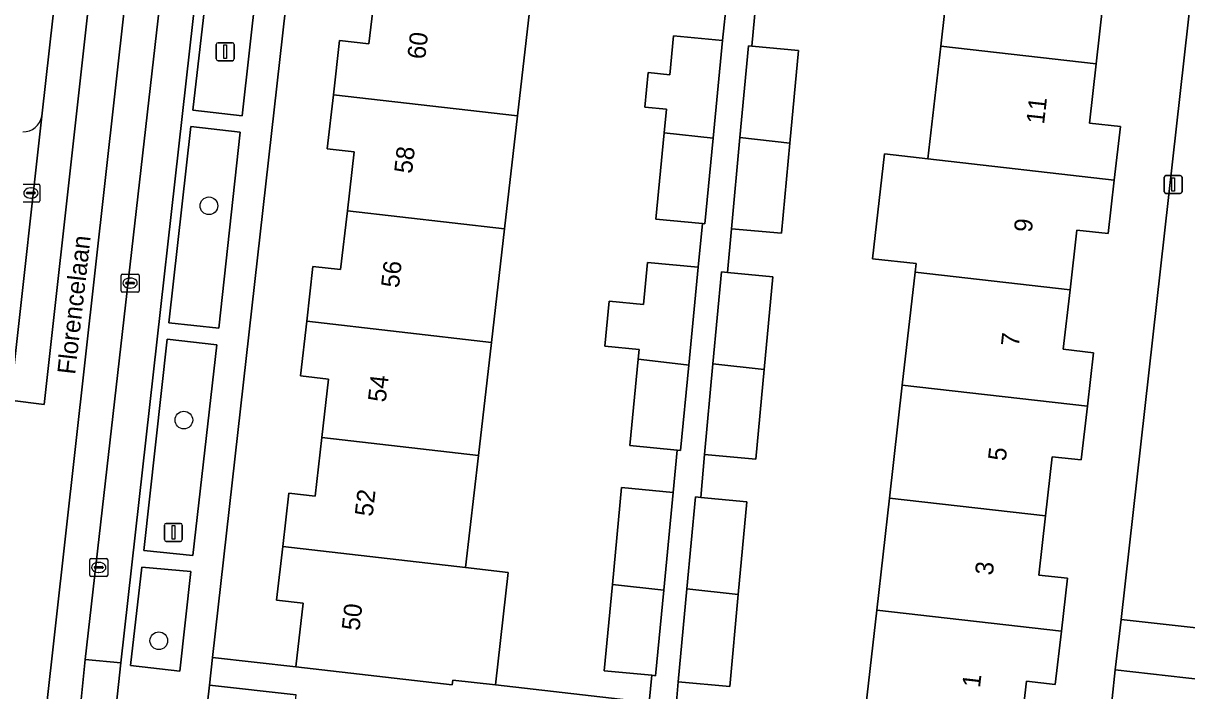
# Model space of a CAD drawing. Extents: x 162082 to 163401, y 388089 to 388636.
# Drawn here: x 162729.5 to 162794, y 388507 to 388544.1 of the extents above; entities that cross this region are included whole.
import ezdxf

# ---------------------------------------------------------------- set-up
doc = ezdxf.new("R2010")
doc.units = 0
for name, color, linetype in [('IMGEO_Boom', 7, 'Continuous'), ('IMGEO_Erf', 7, 'Continuous'), ('IMGEO_Groenvoorziening', 7, 'Continuous'), ('IMGEO_Kolk', 7, 'Continuous'), ('IMGEO_Lichtmast', 7, 'Continuous'), ('IMGEO_Openbare_ruimte_label', 7, 'Continuous'), ('IMGEO_Pand', 7, 'Continuous'), ('IMGEO_Pand_nummerreeks', 7, 'Continuous'), ('IMGEO_Parkeervlak_open', 7, 'Continuous'), ('IMGEO_Rijbaan_lokaal_gesloten', 7, 'Continuous'), ('IMGEO_Rijbaan_lokaal_open', 7, 'Continuous'), ('IMGEO_Voetpad_open', 7, 'Continuous')]:
    doc.layers.add(name, color=color, linetype=linetype)

msp = doc.modelspace()

# ---------------------------------------------------------------- linework, layer by layer
at = {"layer": 'IMGEO_Boom'}
for centre in [(162739.754, 388533.943), (162738.364, 388522.057), (162736.974, 388509.816)]:
    msp.add_circle(centre, 0.489, dxfattribs=at)
at = {"layer": 'IMGEO_Erf'}
for points in [[(162745.878, 388561.46), (162739.957, 388508.884), (162744.578, 388508.364), (162744.984, 388511.902), (162743.511, 388512.071), (162743.851, 388515.038), (162744.192, 388518.007), (162745.652, 388517.839), (162746.024, 388521.085), (162746.396, 388524.33), (162744.83, 388524.509), (162745.179, 388527.545), (162745.527, 388530.58), (162747.062, 388530.403), (162747.436, 388533.665), (162747.811, 388536.927), (162746.316, 388537.099), (162746.661, 388540.105), (162747.005, 388543.109), (162748.636, 388542.922), (162749.011, 388546.188)], [(162789.54, 388503.424), (162790.046, 388508.201), (162790.361, 388511.004), (162795.399, 388555.856)], [(162776.059, 388504.867), (162776.811, 388511.504), (162777.516, 388517.726), (162778.226, 388523.988), (162778.937, 388530.267), (162778.99, 388530.733), (162776.58, 388531.006), (162777.238, 388536.817), (162779.648, 388536.543), (162780.357, 388542.8), (162781.07, 388549.092)], [(162757.592, 388545.203), (162756.873, 388538.933), (162756.154, 388532.665), (162755.431, 388526.368), (162754.711, 388520.088), (162753.998, 388513.874), (162756.364, 388513.603), (162755.649, 388507.365), (162764.19, 388506.386), (162764.321, 388507.898), (162761.684, 388508.149), (162762.14, 388512.94), (162762.652, 388518.312), (162765.507, 388518.04), (162765.731, 388520.394), (162763.117, 388520.643), (162763.573, 388525.433), (162763.624, 388525.967), (162761.717, 388526.149), (162761.956, 388528.655), (162763.863, 388528.473), (162764.085, 388530.806), (162766.896, 388530.538), (162767.137, 388532.963), (162764.559, 388533.208), (162765.015, 388537.999), (162765.139, 388539.305), (162763.94, 388539.419), (162764.123, 388541.33), (162765.322, 388541.216), (162765.527, 388543.371), (162768.247, 388543.112), (162768.485, 388545.392)], [(162770.105, 388545.184), (162769.883, 388542.803), (162772.469, 388542.564), (162771.992, 388537.413), (162771.53, 388532.417), (162768.748, 388532.674), (162768.535, 388530.241), (162771.036, 388530.01), (162770.56, 388524.86), (162770.1, 388519.887), (162767.256, 388520.151), (162767.044, 388517.766), (162769.604, 388517.529), (162769.126, 388512.377), (162768.654, 388507.273), (162765.798, 388507.537), (162765.675, 388506.212)], [(162789.362, 388545.114), (162788.988, 388541.82), (162788.615, 388538.527), (162790.327, 388538.333), (162789.991, 388535.368), (162789.655, 388532.398), (162787.908, 388532.596), (162787.534, 388529.29), (162787.159, 388525.984), (162788.833, 388525.794), (162788.496, 388522.82), (162788.159, 388519.844), (162786.549, 388520.026), (162786.177, 388516.742), (162785.805, 388513.462), (162787.385, 388513.283), (162787.051, 388510.34), (162786.717, 388507.393), (162785.114, 388507.574), (162784.697, 388503.888)], [(162786.382, 388500.073), (162786.604, 388502.153), (162781.395, 388502.707), (162781.106, 388500.167), (162776.026, 388500.742), (162771.206, 388501.288), (162771.494, 388503.827), (162768.909, 388504.11), (162768.696, 388501.874), (162763.594, 388502.359), (162758.632, 388502.832), (162758.858, 388505.209), (162756.271, 388505.492), (162755.985, 388502.961), (162750.924, 388503.535), (162744.309, 388504.284), (162744.595, 388506.815), (162739.785, 388507.361), (162737.36, 388485.969)]]:
    msp.add_lwpolyline(points, dxfattribs=at)
at = {"layer": 'IMGEO_Groenvoorziening'}
for points in [[(162742.779, 388549.542), (162740.074, 388549.861), (162738.863, 388539.243), (162741.596, 388538.927)], [(162741.489, 388538.023), (162738.747, 388538.334), (162737.538, 388527.456), (162740.301, 388527.149)], [(162740.194, 388526.236), (162737.436, 388526.539), (162736.136, 388514.826), (162738.86, 388514.54)], [(162738.748, 388513.664), (162736.03, 388513.903), (162735.408, 388508.44), (162738.139, 388508.128)]]:
    msp.add_lwpolyline(points, close=True, dxfattribs=at)
at = {"layer": 'IMGEO_Kolk'}
for p, q in [((162729.454, 388535.151), (162730.306, 388535.151)), ((162729.867, 388534.931), (162729.892, 388534.931)), ((162730.38, 388535.077), (162730.38, 388534.225)), ((162729.638, 388534.645), (162729.638, 388534.657)), ((162730.076, 388534.608), (162729.678, 388534.608)), ((162729.681, 388534.694), (162730.079, 388534.694)), ((162729.89, 388534.371), (162729.865, 388534.371)), ((162730.122, 388534.657), (162730.122, 388534.645)), ((162730.306, 388534.151), (162729.454, 388534.151)), ((162734.878, 388529.229), (162734.878, 388530.081)), ((162734.953, 388530.155), (162735.805, 388530.155)), ((162735.366, 388529.935), (162735.391, 388529.935)), ((162735.879, 388530.081), (162735.879, 388529.229)), ((162735.805, 388529.155), (162734.953, 388529.155)), ((162735.137, 388529.649), (162735.137, 388529.661)), ((162735.575, 388529.612), (162735.177, 388529.612)), ((162735.18, 388529.698), (162735.578, 388529.698)), ((162735.389, 388529.375), (162735.364, 388529.375)), ((162735.621, 388529.661), (162735.621, 388529.649)), ((162733.138, 388513.459), (162733.138, 388514.311)), ((162733.213, 388514.385), (162734.065, 388514.385)), ((162734.139, 388514.311), (162734.139, 388513.459)), ((162733.397, 388513.879), (162733.397, 388513.891)), ((162733.835, 388513.842), (162733.437, 388513.842)), ((162733.44, 388513.928), (162733.838, 388513.928)), ((162733.626, 388514.165), (162733.651, 388514.165)), ((162733.881, 388513.891), (162733.881, 388513.879)), ((162734.065, 388513.385), (162733.213, 388513.385)), ((162733.649, 388513.605), (162733.624, 388513.605))]:
    msp.add_line(p, q, dxfattribs=at)
for points in [[(162729.454, 388535.151), (162730.306, 388535.151)], [(162730.38, 388535.077), (162730.38, 388534.225)], [(162730.306, 388534.151), (162729.454, 388534.151)], [(162734.878, 388529.229), (162734.878, 388530.081)], [(162734.953, 388530.155), (162735.805, 388530.155)], [(162735.879, 388530.081), (162735.879, 388529.229)], [(162735.805, 388529.155), (162734.953, 388529.155)], [(162733.138, 388513.459), (162733.138, 388514.311)], [(162733.213, 388514.385), (162734.065, 388514.385)], [(162734.139, 388514.311), (162734.139, 388513.459)], [(162734.065, 388513.385), (162733.213, 388513.385)]]:
    msp.add_lwpolyline(points, dxfattribs=at)
for centre, radius, start, end in [((162730.304, 388535.075), 0.0765, 1.55205, 88.44795), ((162730.304, 388535.075), 0.0765, 1.55205, 88.44795), ((162729.678, 388534.654), 0.0403, 85.87752, 175.75265), ((162729.675, 388534.644), 0.0366, 178.93798, 274.71019), ((162730.079, 388534.651), 0.043, 264.86636, 352.45326), ((162730.083, 388534.656), 0.0386, 1.73085, 96.63898), ((162730.304, 388534.227), 0.0765, 271.55205, 358.44795), ((162730.304, 388534.227), 0.0765, 271.55205, 358.44795), ((162734.955, 388530.079), 0.0765, 91.55205, 178.44795), ((162734.955, 388530.079), 0.0765, 91.55205, 178.44795), ((162735.803, 388530.079), 0.0765, 1.55205, 88.44795), ((162735.803, 388530.079), 0.0765, 1.55205, 88.44795), ((162734.955, 388529.231), 0.0765, 181.55205, 268.44795), ((162734.955, 388529.231), 0.0765, 181.55205, 268.44795), ((162735.177, 388529.658), 0.0403, 85.87752, 175.75265), ((162735.174, 388529.648), 0.0366, 178.93798, 274.71019), ((162735.578, 388529.655), 0.043, 264.86636, 352.45326), ((162735.582, 388529.66), 0.0386, 1.73085, 96.63898), ((162735.803, 388529.231), 0.0765, 271.55205, 358.44795), ((162735.803, 388529.231), 0.0765, 271.55205, 358.44795), ((162733.215, 388514.309), 0.0765, 91.55205, 178.44795), ((162733.215, 388514.309), 0.0765, 91.55205, 178.44795), ((162734.063, 388514.309), 0.0765, 1.55205, 88.44795), ((162734.063, 388514.309), 0.0765, 1.55205, 88.44795), ((162733.437, 388513.888), 0.0403, 85.87752, 175.75265), ((162733.434, 388513.878), 0.0366, 178.93798, 274.71019), ((162733.838, 388513.885), 0.043, 264.86636, 352.45326), ((162733.842, 388513.89), 0.0386, 1.73085, 96.63898), ((162733.215, 388513.461), 0.0765, 181.55205, 268.44795), ((162733.215, 388513.461), 0.0765, 181.55205, 268.44795), ((162734.063, 388513.461), 0.0765, 271.55205, 358.44795), ((162734.063, 388513.461), 0.0765, 271.55205, 358.44795)]:
    msp.add_arc(centre, radius, start, end, dxfattribs=at)
for centre, major_axis, ratio, start_param, end_param in [((162729.866, 388534.651), (-0.387, 0.002), 0.722429, 4.712389, 7.853982), ((162729.891, 388534.651), (-0.39, 0.002), 0.717154, 1.570796, 4.712389), ((162735.365, 388529.655), (-0.387, 0.002), 0.722429, 4.712389, 7.853982), ((162735.39, 388529.655), (-0.39, 0.002), 0.717154, 1.570796, 4.712389), ((162733.625, 388513.885), (-0.387, 0.002), 0.722429, 4.712389, 7.853982), ((162733.65, 388513.885), (-0.39, 0.002), 0.717154, 1.570796, 4.712389)]:
    msp.add_ellipse(centre, major_axis=major_axis, ratio=ratio, start_param=start_param, end_param=end_param, dxfattribs=at)
at = {"layer": 'IMGEO_Lichtmast'}
for p, q in [((162740.164, 388542.087), (162740.164, 388542.887)), ((162740.164, 388542.887), (162740.164, 388542.087)), ((162740.264, 388542.987), (162741.054, 388542.987)), ((162741.054, 388542.987), (162740.264, 388542.987)), ((162741.154, 388542.887), (162741.154, 388542.087)), ((162741.154, 388542.087), (162741.154, 388542.887)), ((162741.054, 388541.987), (162740.264, 388541.987)), ((162740.264, 388541.987), (162741.054, 388541.987)), ((162792.856, 388535.624), (162793.646, 388535.624)), ((162793.646, 388535.624), (162792.856, 388535.624)), ((162792.756, 388534.724), (162792.756, 388535.524)), ((162792.756, 388535.524), (162792.756, 388534.724)), ((162793.746, 388535.524), (162793.746, 388534.724)), ((162793.746, 388534.724), (162793.746, 388535.524)), ((162793.646, 388534.624), (162792.856, 388534.624)), ((162792.856, 388534.624), (162793.646, 388534.624)), ((162737.288, 388515.425), (162737.288, 388516.225)), ((162737.288, 388516.225), (162737.288, 388515.425)), ((162737.388, 388516.325), (162738.178, 388516.325)), ((162738.178, 388516.325), (162737.388, 388516.325)), ((162738.278, 388516.225), (162738.278, 388515.425)), ((162738.278, 388515.425), (162738.278, 388516.225)), ((162738.178, 388515.325), (162737.388, 388515.325)), ((162737.388, 388515.325), (162738.178, 388515.325))]:
    msp.add_line(p, q, dxfattribs=at)
for points in [[(162740.584, 388542.862), (162740.734, 388542.862), (162740.734, 388542.112), (162740.584, 388542.112), (162740.584, 388542.862)], [(162793.176, 388535.499), (162793.326, 388535.499), (162793.326, 388534.749), (162793.176, 388534.749), (162793.176, 388535.499)], [(162737.708, 388516.2), (162737.858, 388516.2), (162737.858, 388515.45), (162737.708, 388515.45), (162737.708, 388516.2)]]:
    msp.add_lwpolyline(points, dxfattribs=at)
for centre, start, end in [((162740.264, 388542.887), 90, 180), ((162740.264, 388542.887), 90, 180), ((162741.054, 388542.887), 0, 90), ((162741.054, 388542.887), 360, 90), ((162740.264, 388542.087), 180, 270), ((162740.264, 388542.087), 180, 270), ((162741.054, 388542.087), 270, 0), ((162741.054, 388542.087), 270, 0), ((162792.856, 388535.524), 90, 180), ((162792.856, 388535.524), 90, 180), ((162793.646, 388535.524), 0, 90), ((162793.646, 388535.524), 360, 90), ((162792.856, 388534.724), 180, 270), ((162792.856, 388534.724), 180, 270), ((162793.646, 388534.724), 270, 0), ((162793.646, 388534.724), 270, 0), ((162737.388, 388516.225), 90, 180), ((162737.388, 388516.225), 90, 180), ((162738.178, 388516.225), 0, 90), ((162738.178, 388516.225), 360, 90), ((162737.388, 388515.425), 180, 270), ((162737.388, 388515.425), 180, 270), ((162738.178, 388515.425), 270, 0), ((162738.178, 388515.425), 270, 0)]:
    msp.add_arc(centre, 0.1, start, end, dxfattribs=at)
at = {"layer": 'IMGEO_Pand'}
for points in [[(162780.357, 388542.8), (162788.988, 388541.82), (162789.362, 388545.114), (162790.955, 388544.934), (162791.295, 388547.93), (162781.07, 388549.092)], [(162749.011, 388546.188), (162748.636, 388542.922), (162747.005, 388543.109), (162746.661, 388540.105), (162756.873, 388538.933), (162757.592, 388545.203)], [(162768.247, 388543.112), (162765.527, 388543.371), (162765.322, 388541.216), (162764.123, 388541.33), (162763.94, 388539.419), (162765.139, 388539.305), (162765.015, 388537.999), (162767.73, 388537.687)], [(162769.883, 388542.803), (162769.688, 388542.821), (162769.216, 388537.728), (162771.992, 388537.413), (162772.469, 388542.564)], [(162779.648, 388536.543), (162789.991, 388535.368), (162790.327, 388538.333), (162788.615, 388538.527), (162788.988, 388541.82), (162780.357, 388542.8)], [(162756.154, 388532.665), (162756.873, 388538.933), (162746.661, 388540.105), (162746.316, 388537.099), (162747.811, 388536.927), (162747.436, 388533.665)], [(162767.73, 388537.687), (162765.015, 388537.999), (162764.559, 388533.208), (162767.137, 388532.963), (162767.279, 388532.949)], [(162771.992, 388537.413), (162769.216, 388537.728), (162768.748, 388532.674), (162771.53, 388532.417)], [(162789.991, 388535.368), (162779.648, 388536.543), (162777.238, 388536.817), (162776.58, 388531.006), (162778.99, 388530.733), (162778.937, 388530.267), (162787.534, 388529.29), (162787.908, 388532.596), (162789.655, 388532.398)], [(162745.179, 388527.545), (162755.431, 388526.368), (162756.154, 388532.665), (162747.436, 388533.665), (162747.062, 388530.403), (162745.527, 388530.58)], [(162766.896, 388530.538), (162764.085, 388530.806), (162763.863, 388528.473), (162761.956, 388528.655), (162761.717, 388526.149), (162763.624, 388525.967), (162763.573, 388525.433), (162766.259, 388525.125), (162766.379, 388525.111)], [(162768.535, 388530.241), (162768.193, 388530.273), (162767.722, 388525.183), (162770.56, 388524.86), (162771.036, 388530.01)], [(162778.937, 388530.267), (162778.226, 388523.988), (162788.496, 388522.82), (162788.833, 388525.794), (162787.159, 388525.984), (162787.534, 388529.29)], [(162746.024, 388521.085), (162754.711, 388520.088), (162755.431, 388526.368), (162745.179, 388527.545), (162744.83, 388524.509), (162746.396, 388524.33)], [(162766.379, 388525.111), (162766.259, 388525.125), (162763.573, 388525.433), (162763.117, 388520.643), (162765.731, 388520.394), (162765.928, 388520.375)], [(162770.56, 388524.86), (162767.722, 388525.183), (162767.256, 388520.151), (162770.1, 388519.887)], [(162778.226, 388523.988), (162777.516, 388517.726), (162786.177, 388516.742), (162786.549, 388520.026), (162788.159, 388519.844), (162788.496, 388522.82)], [(162743.851, 388515.038), (162753.998, 388513.874), (162754.711, 388520.088), (162746.024, 388521.085), (162745.652, 388517.839), (162744.192, 388518.007)], [(162765.507, 388518.04), (162762.652, 388518.312), (162762.14, 388512.94), (162764.99, 388512.613)], [(162767.044, 388517.766), (162766.748, 388517.793), (162766.276, 388512.701), (162769.126, 388512.377), (162769.604, 388517.529)], [(162777.516, 388517.726), (162776.811, 388511.504), (162787.051, 388510.34), (162787.385, 388513.283), (162785.805, 388513.462), (162786.177, 388516.742)], [(162753.998, 388513.874), (162743.851, 388515.038), (162743.511, 388512.071), (162744.984, 388511.902), (162744.578, 388508.364), (162749.546, 388507.793), (162753.251, 388507.368), (162753.282, 388507.637), (162755.649, 388507.365), (162756.364, 388513.603)], [(162764.99, 388512.613), (162762.14, 388512.94), (162761.684, 388508.149), (162764.321, 388507.898), (162764.539, 388507.877)], [(162769.126, 388512.377), (162766.276, 388512.701), (162765.798, 388507.537), (162768.654, 388507.273)], [(162776.811, 388511.504), (162776.059, 388504.867), (162779.729, 388504.451), (162784.697, 388503.888), (162785.114, 388507.574), (162786.717, 388507.393), (162787.051, 388510.34)]]:
    msp.add_lwpolyline(points, close=True, dxfattribs=at)
at = {"layer": 'IMGEO_Parkeervlak_open'}
for points in [[(162738.143, 388554.92), (162732.894, 388508.771), (162734.876, 388508.583), (162739.881, 388553.247)], [(162728.958, 388525.087), (162730.483, 388538.918)]]:
    msp.add_lwpolyline(points, dxfattribs=at)
msp.add_arc((162729.452, 388539.09), 1.045, 268.47356, 350.52823, dxfattribs=at)
at = {"layer": 'IMGEO_Rijbaan_lokaal_gesloten'}
for points in [[(162732.326, 388555.585), (162731.742, 388550.144), (162730.483, 388538.918), (162728.958, 388525.087), (162728.711, 388523.165), (162730.61, 388522.925), (162734.225, 388555.356)], [(162732.479, 388504.706), (162732.894, 388508.771), (162738.143, 388554.92), (162736.204, 388555.092), (162728.485, 388485.946), (162730.347, 388485.702), (162730.675, 388488.87), (162730.922, 388491.017)]]:
    msp.add_lwpolyline(points, close=True, dxfattribs=at)
at = {"layer": 'IMGEO_Rijbaan_lokaal_open'}
for points in [[(162738.116, 388555.378), (162738.231, 388556.314), (162732.478, 388556.998), (162732.326, 388555.585), (162734.225, 388555.356), (162730.61, 388522.925), (162728.711, 388523.165)], [(162730.347, 388485.702), (162728.485, 388485.946), (162736.204, 388555.092), (162738.143, 388554.92)]]:
    msp.add_lwpolyline(points, dxfattribs=at)
for points in [[(162800.285, 388545.207), (162801.378, 388555.202), (162795.399, 388555.856), (162790.361, 388511.004), (162798.188, 388510.125), (162799.75, 388524.546), (162800.627, 388530.409), (162798.588, 388530.623)], [(162797.884, 388507.321), (162798.188, 388510.125), (162790.361, 388511.004), (162790.046, 388508.201)], [(162734.876, 388508.583), (162732.894, 388508.771), (162732.479, 388504.706), (162734.427, 388504.473)], [(162797.091, 388500), (162797.153, 388500.577), (162797.333, 388502.233), (162797.884, 388507.321), (162790.046, 388508.201), (162789.54, 388503.424), (162789.374, 388501.858), (162789.139, 388499.763), (162786.727, 388478.655), (162794.676, 388477.705)]]:
    msp.add_lwpolyline(points, close=True, dxfattribs=at)
at = {"layer": 'IMGEO_Voetpad_open'}
for points in [[(162737.36, 388485.969), (162739.785, 388507.361), (162739.957, 388508.884), (162745.878, 388561.46), (162744.217, 388562.343), (162739.286, 388562.889)], [(162738.723, 388560.481), (162738.473, 388558.431), (162743.715, 388557.817), (162742.877, 388550.452), (162740.156, 388550.803), (162740.405, 388553.228), (162739.881, 388553.247), (162734.876, 388508.583), (162734.427, 388504.473), (162733.107, 388492.654), (162733.087, 388492.504), (162733.629, 388492.476), (162734.226, 388497.626), (162736.893, 388497.327), (162734.928, 388479.401)], [(162730.483, 388538.918), (162731.742, 388550.144), (162732.326, 388555.585)], [(162768.485, 388545.392), (162768.247, 388543.112), (162767.73, 388537.687), (162767.279, 388532.949), (162767.137, 388532.963), (162766.896, 388530.538), (162766.379, 388525.111), (162765.928, 388520.375), (162765.731, 388520.394), (162765.507, 388518.04), (162764.99, 388512.613), (162764.539, 388507.877), (162764.321, 388507.898), (162764.19, 388506.386), (162755.649, 388507.365), (162753.282, 388507.637), (162753.251, 388507.368), (162749.546, 388507.793), (162744.578, 388508.364), (162739.957, 388508.884), (162739.785, 388507.361), (162744.595, 388506.815)], [(162765.675, 388506.212), (162765.798, 388507.537), (162766.276, 388512.701), (162766.748, 388517.793), (162767.044, 388517.766), (162767.256, 388520.151), (162767.722, 388525.183), (162768.193, 388530.273), (162768.535, 388530.241), (162768.748, 388532.674), (162769.216, 388537.728), (162769.688, 388542.821), (162769.883, 388542.803), (162770.105, 388545.184)]]:
    msp.add_lwpolyline(points, dxfattribs=at)
for points in [[(162742.779, 388549.542), (162741.596, 388538.927), (162738.863, 388539.243), (162740.074, 388549.861)], [(162741.489, 388538.023), (162740.301, 388527.149), (162737.538, 388527.456), (162738.747, 388538.334)], [(162740.194, 388526.236), (162738.86, 388514.54), (162736.136, 388514.826), (162737.436, 388526.539)], [(162738.748, 388513.664), (162738.139, 388508.128), (162735.408, 388508.44), (162736.03, 388513.903)]]:
    msp.add_lwpolyline(points, close=True, dxfattribs=at)
msp.add_arc((162729.452, 388539.09), 1.045, 268.47356, 350.52823, dxfattribs=at)

# ---------------------------------------------------------------- texts
at = {"layer": 'IMGEO_Openbare_ruimte_label'}
msp.add_text('Florencelaan', height=1, rotation=83.57125, dxfattribs=at).set_placement((162732.331, 388524.556))
at = {"layer": 'IMGEO_Pand_nummerreeks'}
for s, rotation, p in [('60', 83.44451, (162751.749, 388542.038)), ('11', 83.51199, (162786.09, 388538.437)), ('58', 83.44451, (162751.02, 388535.699)), ('9', 83.51433, (162785.408, 388532.438)), ('56', 83.44451, (162750.292, 388529.357)), ('7', 83.51199, (162784.687, 388526.096)), ('54', 83.44451, (162749.563, 388523.017)), ('5', 83.51199, (162783.966, 388519.754)), ('52', 83.44451, (162748.834, 388516.675)), ('3', 83.51199, (162783.244, 388513.412)), ('50', 83.44557, (162748.107, 388510.342)), ('1', 83.51199, (162782.535, 388507.183))]:
    msp.add_text(s, height=1, rotation=rotation, dxfattribs=at).set_placement(p)

doc.saveas('drawing.dxf')
